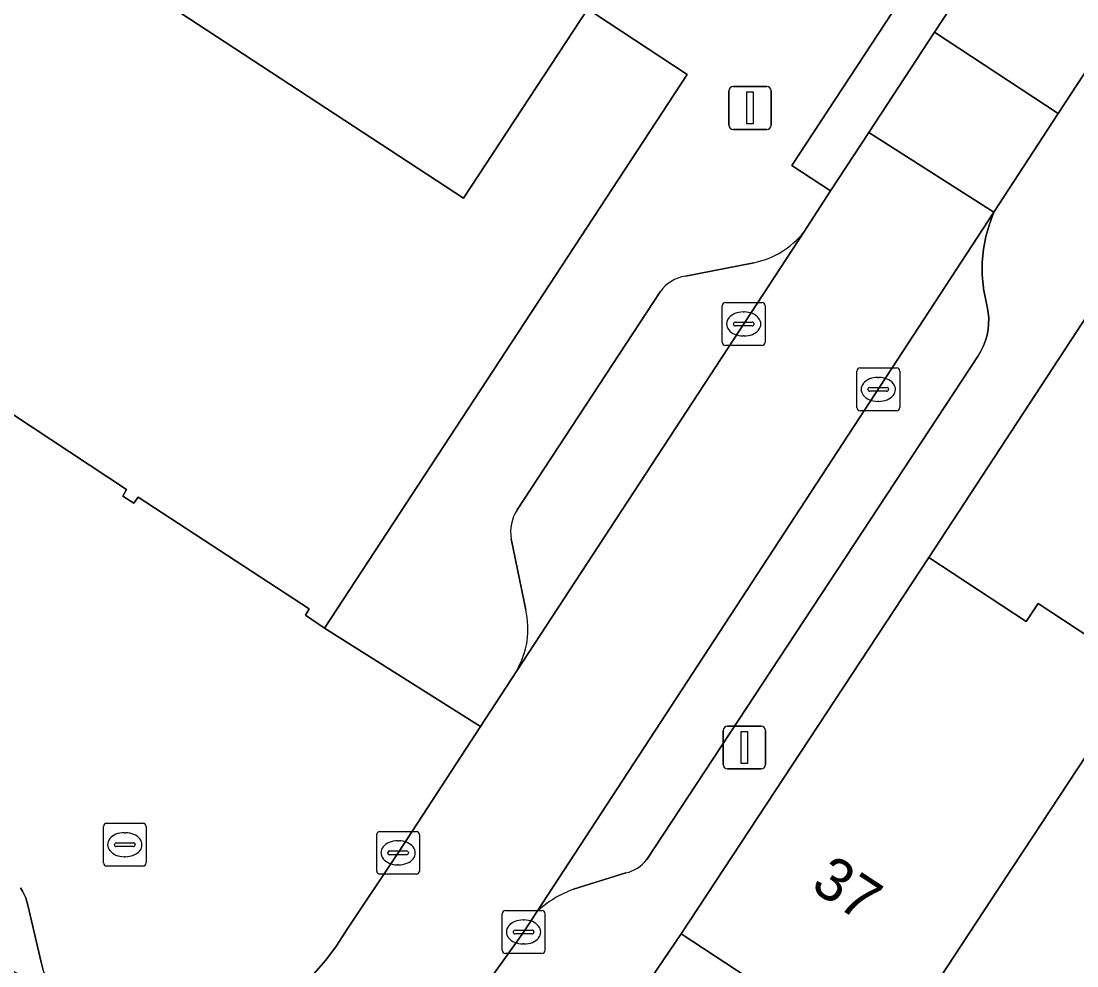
# Model space of a CAD drawing. Extents: x 159279 to 160377, y 384531 to 385888.
# Drawn here: x 159802.09 to 159826.76, y 385019.34 to 385041.4 of the extents above; entities that cross this region are included whole.
import ezdxf

# ---------------------------------------------------------------- set-up
doc = ezdxf.new("R2010")
doc.units = 0
for name, color, linetype in [('IMGEO_Brandkraan', 7, 'Continuous'), ('IMGEO_Erf', 7, 'Continuous'), ('IMGEO_Kolk', 7, 'Continuous'), ('IMGEO_Lichtmast', 7, 'Continuous'), ('IMGEO_Muur', 7, 'Continuous'), ('IMGEO_Pand', 7, 'Continuous'), ('IMGEO_Pand_nummerreeks', 7, 'Continuous'), ('IMGEO_Parkeervlak_open', 7, 'Continuous'), ('IMGEO_Rijbaan_lokaal_open', 7, 'Continuous'), ('IMGEO_Voetpad_open', 7, 'Continuous')]:
    doc.layers.add(name, color=color, linetype=linetype)

msp = doc.modelspace()

# ---------------------------------------------------------------- linework, layer by layer
at = {"layer": 'IMGEO_Brandkraan'}
for p, q in [((159804.013, 385021.739), (159804.013, 385022.591)), ((159804.088, 385022.665), (159804.94, 385022.665)), ((159805.014, 385022.591), (159805.014, 385021.739)), ((159804.501, 385022.445), (159804.526, 385022.445)), ((159804.272, 385022.159), (159804.272, 385022.171)), ((159804.71, 385022.122), (159804.312, 385022.122)), ((159804.315, 385022.208), (159804.713, 385022.208)), ((159804.756, 385022.171), (159804.756, 385022.159)), ((159804.524, 385021.885), (159804.499, 385021.885)), ((159804.94, 385021.665), (159804.088, 385021.665))]:
    msp.add_line(p, q, dxfattribs=at)
for points in [[(159804.013, 385021.739), (159804.013, 385022.591)], [(159804.088, 385022.665), (159804.94, 385022.665)], [(159805.014, 385022.591), (159805.014, 385021.739)], [(159804.94, 385021.665), (159804.088, 385021.665)]]:
    msp.add_lwpolyline(points, dxfattribs=at)
for centre, radius, start, end in [((159804.09, 385022.589), 0.0765, 91.552, 178.448), ((159804.09, 385022.589), 0.0765, 91.552, 178.448), ((159804.938, 385022.589), 0.0765, 1.552, 88.448), ((159804.938, 385022.589), 0.0765, 1.552, 88.448), ((159804.312, 385022.168), 0.0403, 85.8775, 175.7526), ((159804.309, 385022.158), 0.0366, 178.938, 274.7102), ((159804.713, 385022.165), 0.043, 264.8664, 352.4533), ((159804.717, 385022.17), 0.0386, 1.7309, 96.639), ((159804.09, 385021.741), 0.0765, 181.552, 268.448), ((159804.09, 385021.741), 0.0765, 181.552, 268.448), ((159804.938, 385021.741), 0.0765, 271.552, 358.448), ((159804.938, 385021.741), 0.0765, 271.552, 358.448)]:
    msp.add_arc(centre, radius, start, end, dxfattribs=at)
for centre, major_axis, ratio, start_param, end_param in [((159804.5, 385022.165), (-0.387, 0.002), 0.722429, 4.712389, 7.853982), ((159804.525, 385022.165), (-0.39, 0.002), 0.717154, 1.570796, 4.712389)]:
    msp.add_ellipse(centre, major_axis=major_axis, ratio=ratio, start_param=start_param, end_param=end_param, dxfattribs=at)
at = {"layer": 'IMGEO_Erf'}
msp.add_lwpolyline([(159829.652, 385038.574), (159823.296, 385028.874), (159825.576, 385027.374), (159825.854, 385027.797), (159828.268, 385026.209)], dxfattribs=at)
msp.add_lwpolyline([(159840.578, 385004.911), (159835.985, 385007.933), (159831.393, 385010.954), (159826.8, 385013.976), (159822.207, 385016.998), (159817.514, 385020.085), (159815.287, 385016.806), (159840.869, 385000), (159866.078, 384983.439), (159868.234, 384986.716), (159863.541, 384989.803), (159858.949, 384992.825), (159854.356, 384995.846), (159849.763, 384998.868), (159848.043, 385000), (159845.17, 385001.89)], close=True, dxfattribs=at)
at = {"layer": 'IMGEO_Kolk'}
for p, q in [((159818.473, 385033.899), (159818.473, 385034.751)), ((159818.548, 385034.825), (159819.4, 385034.825)), ((159818.961, 385034.605), (159818.986, 385034.605)), ((159819.474, 385034.751), (159819.474, 385033.899)), ((159818.775, 385034.368), (159819.173, 385034.368)), ((159818.732, 385034.319), (159818.732, 385034.331)), ((159819.17, 385034.282), (159818.772, 385034.282)), ((159819.216, 385034.331), (159819.216, 385034.319)), ((159818.984, 385034.045), (159818.959, 385034.045)), ((159819.4, 385033.825), (159818.548, 385033.825)), ((159821.618, 385032.371), (159821.618, 385033.223)), ((159821.693, 385033.297), (159822.545, 385033.297)), ((159822.619, 385033.223), (159822.619, 385032.371)), ((159822.106, 385033.077), (159822.131, 385033.077)), ((159821.877, 385032.791), (159821.877, 385032.803)), ((159822.315, 385032.754), (159821.917, 385032.754)), ((159821.92, 385032.84), (159822.318, 385032.84)), ((159822.361, 385032.803), (159822.361, 385032.791)), ((159822.129, 385032.517), (159822.104, 385032.517)), ((159822.545, 385032.297), (159821.693, 385032.297)), ((159810.399, 385021.549), (159810.399, 385022.401)), ((159810.474, 385022.475), (159811.326, 385022.475)), ((159810.887, 385022.255), (159810.912, 385022.255)), ((159811.4, 385022.401), (159811.4, 385021.549)), ((159810.701, 385022.018), (159811.099, 385022.018)), ((159810.658, 385021.969), (159810.658, 385021.981)), ((159811.096, 385021.932), (159810.698, 385021.932)), ((159811.142, 385021.981), (159811.142, 385021.969)), ((159810.91, 385021.695), (159810.885, 385021.695)), ((159811.326, 385021.475), (159810.474, 385021.475)), ((159813.33, 385019.701), (159813.33, 385020.553)), ((159813.405, 385020.627), (159814.257, 385020.627)), ((159814.331, 385020.553), (159814.331, 385019.701)), ((159813.818, 385020.407), (159813.843, 385020.407)), ((159813.589, 385020.121), (159813.589, 385020.133)), ((159814.027, 385020.084), (159813.629, 385020.084)), ((159813.632, 385020.17), (159814.03, 385020.17)), ((159814.073, 385020.133), (159814.073, 385020.121)), ((159813.841, 385019.847), (159813.816, 385019.847)), ((159814.257, 385019.627), (159813.405, 385019.627))]:
    msp.add_line(p, q, dxfattribs=at)
for points in [[(159818.473, 385033.899), (159818.473, 385034.751)], [(159818.548, 385034.825), (159819.4, 385034.825)], [(159819.474, 385034.751), (159819.474, 385033.899)], [(159819.4, 385033.825), (159818.548, 385033.825)], [(159821.618, 385032.371), (159821.618, 385033.223)], [(159821.693, 385033.297), (159822.545, 385033.297)], [(159822.619, 385033.223), (159822.619, 385032.371)], [(159822.545, 385032.297), (159821.693, 385032.297)], [(159810.399, 385021.549), (159810.399, 385022.401)], [(159810.474, 385022.475), (159811.326, 385022.475)], [(159811.4, 385022.401), (159811.4, 385021.549)], [(159811.326, 385021.475), (159810.474, 385021.475)], [(159813.33, 385019.701), (159813.33, 385020.553)], [(159813.405, 385020.627), (159814.257, 385020.627)], [(159814.331, 385020.553), (159814.331, 385019.701)], [(159814.257, 385019.627), (159813.405, 385019.627)]]:
    msp.add_lwpolyline(points, dxfattribs=at)
for centre, radius, start, end in [((159818.55, 385034.749), 0.0765, 91.552, 178.448), ((159818.55, 385034.749), 0.0765, 91.552, 178.448), ((159819.398, 385034.749), 0.0765, 1.552, 88.448), ((159819.398, 385034.749), 0.0765, 1.552, 88.448), ((159818.772, 385034.328), 0.0403, 85.8775, 175.7526), ((159819.177, 385034.33), 0.0386, 1.7309, 96.639), ((159818.769, 385034.318), 0.0366, 178.938, 274.7102), ((159819.173, 385034.325), 0.043, 264.8664, 352.4533), ((159818.55, 385033.901), 0.0765, 181.552, 268.448), ((159818.55, 385033.901), 0.0765, 181.552, 268.448), ((159819.398, 385033.901), 0.0765, 271.552, 358.448), ((159819.398, 385033.901), 0.0765, 271.552, 358.448), ((159821.695, 385033.221), 0.0765, 91.552, 178.448), ((159821.695, 385033.221), 0.0765, 91.552, 178.448), ((159822.543, 385033.221), 0.0765, 1.552, 88.448), ((159822.543, 385033.221), 0.0765, 1.552, 88.448), ((159821.917, 385032.8), 0.0403, 85.8775, 175.7526), ((159821.914, 385032.79), 0.0366, 178.938, 274.7102), ((159822.318, 385032.797), 0.043, 264.8664, 352.4533), ((159822.322, 385032.802), 0.0386, 1.7309, 96.639), ((159821.695, 385032.373), 0.0765, 181.552, 268.448), ((159821.695, 385032.373), 0.0765, 181.552, 268.448), ((159822.543, 385032.373), 0.0765, 271.552, 358.448), ((159822.543, 385032.373), 0.0765, 271.552, 358.448), ((159810.476, 385022.399), 0.0765, 91.552, 178.448), ((159810.476, 385022.399), 0.0765, 91.552, 178.448), ((159811.324, 385022.399), 0.0765, 1.552, 88.448), ((159811.324, 385022.399), 0.0765, 1.552, 88.448), ((159810.698, 385021.978), 0.0403, 85.8775, 175.7526), ((159811.103, 385021.98), 0.0386, 1.7309, 96.639), ((159810.695, 385021.968), 0.0366, 178.938, 274.7102), ((159811.099, 385021.975), 0.043, 264.8664, 352.4533), ((159810.476, 385021.551), 0.0765, 181.552, 268.448), ((159810.476, 385021.551), 0.0765, 181.552, 268.448), ((159811.324, 385021.551), 0.0765, 271.552, 358.448), ((159811.324, 385021.551), 0.0765, 271.552, 358.448), ((159813.407, 385020.551), 0.0765, 91.552, 178.448), ((159813.407, 385020.551), 0.0765, 91.552, 178.448), ((159814.255, 385020.551), 0.0765, 1.552, 88.448), ((159814.255, 385020.551), 0.0765, 1.552, 88.448), ((159813.629, 385020.13), 0.0403, 85.8775, 175.7526), ((159813.626, 385020.12), 0.0366, 178.938, 274.7102), ((159814.03, 385020.127), 0.043, 264.8664, 352.4533), ((159814.034, 385020.132), 0.0386, 1.7309, 96.639), ((159813.407, 385019.703), 0.0765, 181.552, 268.448), ((159813.407, 385019.703), 0.0765, 181.552, 268.448), ((159814.255, 385019.703), 0.0765, 271.552, 358.448), ((159814.255, 385019.703), 0.0765, 271.552, 358.448)]:
    msp.add_arc(centre, radius, start, end, dxfattribs=at)
for centre, major_axis, ratio, start_param, end_param in [((159818.96, 385034.325), (-0.387, 0.002), 0.722429, 4.712389, 7.853982), ((159818.985, 385034.325), (-0.39, 0.002), 0.717154, 1.570796, 4.712389), ((159822.105, 385032.797), (-0.387, 0.002), 0.722429, 4.712389, 7.853982), ((159822.13, 385032.797), (-0.39, 0.002), 0.717154, 1.570796, 4.712389), ((159810.886, 385021.975), (-0.387, 0.002), 0.722429, 4.712389, 7.853982), ((159810.911, 385021.975), (-0.39, 0.002), 0.717154, 1.570796, 4.712389), ((159813.817, 385020.127), (-0.387, 0.002), 0.722429, 4.712389, 7.853982), ((159813.842, 385020.127), (-0.39, 0.002), 0.717154, 1.570796, 4.712389)]:
    msp.add_ellipse(centre, major_axis=major_axis, ratio=ratio, start_param=start_param, end_param=end_param, dxfattribs=at)
at = {"layer": 'IMGEO_Lichtmast'}
for p, q in [((159818.627, 385038.969), (159818.627, 385039.769)), ((159818.627, 385039.769), (159818.627, 385038.969)), ((159818.727, 385039.869), (159819.517, 385039.869)), ((159819.517, 385039.869), (159818.727, 385039.869)), ((159819.617, 385039.769), (159819.617, 385038.969)), ((159819.617, 385038.969), (159819.617, 385039.769)), ((159819.517, 385038.869), (159818.727, 385038.869)), ((159818.727, 385038.869), (159819.517, 385038.869)), ((159818.494, 385024.034), (159818.494, 385024.834)), ((159818.494, 385024.834), (159818.494, 385024.034)), ((159818.594, 385024.934), (159819.384, 385024.934)), ((159819.384, 385024.934), (159818.594, 385024.934)), ((159819.484, 385024.834), (159819.484, 385024.034)), ((159819.484, 385024.034), (159819.484, 385024.834)), ((159819.384, 385023.934), (159818.594, 385023.934)), ((159818.594, 385023.934), (159819.384, 385023.934))]:
    msp.add_line(p, q, dxfattribs=at)
for points in [[(159819.047, 385039.744), (159819.197, 385039.744), (159819.197, 385038.994), (159819.047, 385038.994), (159819.047, 385039.744)], [(159818.914, 385024.809), (159819.064, 385024.809), (159819.064, 385024.059), (159818.914, 385024.059), (159818.914, 385024.809)]]:
    msp.add_lwpolyline(points, dxfattribs=at)
for centre, start, end in [((159818.727, 385039.769), 90, 180), ((159818.727, 385039.769), 90, 180), ((159819.517, 385039.769), 0, 90), ((159819.517, 385039.769), 360, 90), ((159818.727, 385038.969), 180, 270), ((159818.727, 385038.969), 180, 270), ((159819.517, 385038.969), 270, 0), ((159819.517, 385038.969), 270, 0), ((159818.594, 385024.834), 90, 180), ((159818.594, 385024.834), 90, 180), ((159819.384, 385024.834), 0, 90), ((159819.384, 385024.834), 360, 90), ((159818.594, 385024.034), 180, 270), ((159818.594, 385024.034), 180, 270), ((159819.384, 385024.034), 270, 0), ((159819.384, 385024.034), 270, 0)]:
    msp.add_arc(centre, 0.1, start, end, dxfattribs=at)
at = {"layer": 'IMGEO_Muur'}
msp.add_lwpolyline([(159823.296, 385028.874), (159829.652, 385038.574)], dxfattribs=at)
at = {"layer": 'IMGEO_Pand'}
msp.add_lwpolyline([(159800.57, 385033.081), (159804.555, 385030.458), (159804.465, 385030.303), (159804.722, 385030.137), (159804.824, 385030.281), (159808.824, 385027.672), (159808.733, 385027.521), (159809.183, 385027.223), (159817.654, 385040.152), (159815.513, 385041.56), (159815.331, 385041.68), (159812.424, 385037.26), (159759.826, 385071.675)], dxfattribs=at)
for points in [[(159828.035, 385025.855), (159828.268, 385026.209), (159825.854, 385027.797), (159825.576, 385027.374), (159823.296, 385028.874), (159817.514, 385020.085), (159822.207, 385016.998), (159824.921, 385021.123), (159825.511, 385022.02)], [(159831.826, 385021.617), (159829.673, 385023.033), (159830.474, 385024.25), (159828.035, 385025.855), (159825.511, 385022.02), (159824.921, 385021.123), (159822.207, 385016.998), (159826.8, 385013.976), (159829.514, 385018.102)]]:
    msp.add_lwpolyline(points, close=True, dxfattribs=at)
at = {"layer": 'IMGEO_Parkeervlak_open'}
for points in [[(159824.449, 385033.579), (159824.518, 385033.693), (159824.576, 385033.812), (159824.623, 385033.936), (159824.66, 385034.064), (159824.684, 385034.194), (159824.697, 385034.326), (159824.698, 385034.459), (159824.687, 385034.591), (159824.664, 385034.722), (159824.655, 385034.762), (159824.576, 385035.142), (159824.573, 385035.167), (159824.547, 385035.467), (159824.549, 385035.769), (159824.578, 385036.069), (159824.633, 385036.366), (159824.715, 385036.656), (159824.822, 385036.938), (159814.137, 385020.596)], [(159813.67, 385026.228), (159820.378, 385036.469)], [(159776.906, 385035.721), (159803.235, 385018.337), (159803.116, 385018.438), (159803.001, 385018.555), (159802.896, 385018.682), (159802.803, 385018.817), (159802.723, 385018.96), (159802.656, 385019.11), (159802.602, 385019.266), (159802.563, 385019.425), (159802.248, 385020.751), (159802.228, 385020.838), (159802.201, 385020.922), (159802.166, 385021.004), (159802.124, 385021.082), (159802.076, 385021.156)], [(159819.207, 385035.752), (159817.612, 385035.44)], [(159817.023, 385035.074), (159813.684, 385029.981)], [(159816.71, 385021.821), (159824.449, 385033.579)], [(159813.543, 385029.306), (159813.884, 385027.65)], [(159815, 385021.124), (159816.222, 385021.505)]]:
    msp.add_lwpolyline(points, dxfattribs=at)
for centre, radius, start, end in [((159818.8, 385037.731), 2.02, 281.6122, 321.3458), ((159817.727, 385034.598), 0.85, 97.7886, 145.9244), ((159814.428, 385029.473), 0.901, 145.6935, 190.709), ((159811.958, 385027.213), 1.975, 330.0891, 12.7942), ((159816.029, 385022.339), 0.856, 283.0677, 322.7818), ((159815.832, 385018.795), 2.473, 109.6572, 133.261)]:
    msp.add_arc(centre, radius, start, end, dxfattribs=at)
at = {"layer": 'IMGEO_Rijbaan_lokaal_open'}
for points in [[(159759.826, 385071.675), (159812.424, 385037.26), (159815.331, 385041.68), (159815.513, 385041.56), (159819.421, 385047.421), (159811.734, 385052.438), (159808.202, 385054.825), (159805.679, 385056.404), (159806.75, 385058.089), (159810.619, 385064.027), (159811.713, 385065.695), (159812.807, 385067.362), (159816.448, 385072.896), (159815.245, 385073.686), (159813.026, 385075.142), (159810.806, 385076.599), (159809.577, 385077.443), (159807.047, 385079.064), (159800.492, 385083.021)], [(159812.685, 385018.52), (159813.833, 385020.131), (159814.137, 385020.596), (159824.822, 385036.938), (159821.896, 385038.799), (159820.999, 385037.432), (159820.378, 385036.469), (159813.67, 385026.228), (159812.822, 385024.926), (159810.9, 385021.975), (159809.706, 385020.192), (159809.598, 385020.025), (159809.46, 385019.806), (159809.209, 385019.465), (159808.928, 385019.149)]]:
    msp.add_lwpolyline(points, dxfattribs=at)
for points in [[(159842.275, 385063.562), (159839.332, 385065.469), (159825.427, 385044.202), (159825.237, 385043.891), (159823.433, 385041.141), (159826.324, 385039.242), (159826.913, 385040.145), (159831.552, 385047.261), (159832.097, 385048.096)], [(159826.324, 385039.242), (159823.433, 385041.141), (159821.896, 385038.799), (159824.822, 385036.938)]]:
    msp.add_lwpolyline(points, close=True, dxfattribs=at)
at = {"layer": 'IMGEO_Voetpad_open'}
for points in [[(159880.962, 385129.185), (159879.125, 385130.58), (159861.509, 385103.606), (159859.27, 385102.871), (159858.834, 385103.137), (159856.255, 385099.209), (159821.511, 385046.099), (159819.421, 385047.421), (159815.513, 385041.56), (159817.654, 385040.152), (159809.183, 385027.223), (159812.822, 385024.926), (159813.67, 385026.228)], [(159814.137, 385020.596), (159813.833, 385020.131), (159812.685, 385018.52), (159815.287, 385016.806), (159817.514, 385020.085), (159823.296, 385028.874), (159829.652, 385038.574), (159831.172, 385040.875), (159833.719, 385044.747), (159864.782, 385091.975), (159866.293, 385090.902), (159866.572, 385091.228), (159866.721, 385091.454), (159866.868, 385091.678), (159866.05, 385092.216), (159867.679, 385094.69), (159868.498, 385094.15), (159869.401, 385095.52), (159871.061, 385098.154)], [(159832.423, 385046.693), (159827.784, 385039.577), (159826.913, 385040.145), (159826.324, 385039.242), (159824.822, 385036.938), (159824.715, 385036.656), (159824.633, 385036.366), (159824.578, 385036.069), (159824.549, 385035.769), (159824.547, 385035.467), (159824.573, 385035.167), (159824.576, 385035.142), (159824.655, 385034.762), (159824.664, 385034.722), (159824.687, 385034.591), (159824.698, 385034.459), (159824.697, 385034.326), (159824.684, 385034.194), (159824.66, 385034.064), (159824.623, 385033.936), (159824.576, 385033.812), (159824.518, 385033.693), (159824.449, 385033.579), (159816.71, 385021.821)], [(159820.378, 385036.469), (159820.999, 385037.432), (159820.1, 385038.028), (159824.31, 385044.446), (159825.237, 385043.891), (159825.427, 385044.202)], [(159817.612, 385035.44), (159819.207, 385035.752)], [(159813.684, 385029.981), (159817.023, 385035.074)], [(159808.928, 385019.149), (159809.209, 385019.465), (159809.46, 385019.806), (159809.598, 385020.025), (159809.706, 385020.192), (159810.9, 385021.975), (159812.822, 385024.926), (159809.183, 385027.223), (159808.733, 385027.521), (159808.824, 385027.672), (159804.824, 385030.281), (159804.722, 385030.137), (159804.465, 385030.303), (159804.555, 385030.458), (159800.57, 385033.081)], [(159813.884, 385027.65), (159813.543, 385029.306)], [(159816.222, 385021.505), (159815, 385021.124)], [(159802.076, 385021.156), (159802.124, 385021.082), (159802.166, 385021.004), (159802.201, 385020.922), (159802.228, 385020.838), (159802.248, 385020.751), (159802.563, 385019.425), (159802.602, 385019.266)]]:
    msp.add_lwpolyline(points, dxfattribs=at)
msp.add_lwpolyline([(159825.237, 385043.891), (159824.31, 385044.446), (159820.1, 385038.028), (159820.999, 385037.432), (159821.896, 385038.799), (159823.433, 385041.141)], close=True, dxfattribs=at)
for centre, radius, start, end in [((159818.8, 385037.731), 2.02, 281.6122, 321.3458), ((159817.727, 385034.598), 0.85, 97.7886, 145.9244), ((159814.428, 385029.473), 0.901, 145.6935, 190.709), ((159811.958, 385027.213), 1.975, 330.0891, 12.7942), ((159816.029, 385022.339), 0.856, 283.0677, 322.7818), ((159815.832, 385018.795), 2.473, 109.6572, 133.261)]:
    msp.add_arc(centre, radius, start, end, dxfattribs=at)

# ---------------------------------------------------------------- texts
at = {"layer": 'IMGEO_Pand_nummerreeks'}
msp.add_text('37', height=1, rotation=326.6825, dxfattribs=at).set_placement((159820.506, 385021.134))

doc.saveas('drawing.dxf')
